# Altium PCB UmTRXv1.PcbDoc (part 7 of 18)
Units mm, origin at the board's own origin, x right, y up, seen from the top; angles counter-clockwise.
Board outline 172 x 113 mm, 6 copper layers (Top Layer, GND, MidLayer1, Mid-Layer 2, InternalPlane2, Bottom Layer); 766 components, 613 nets, 3008 pads, 1360 vias.
Unrouted connection lines stored in the file: 2.
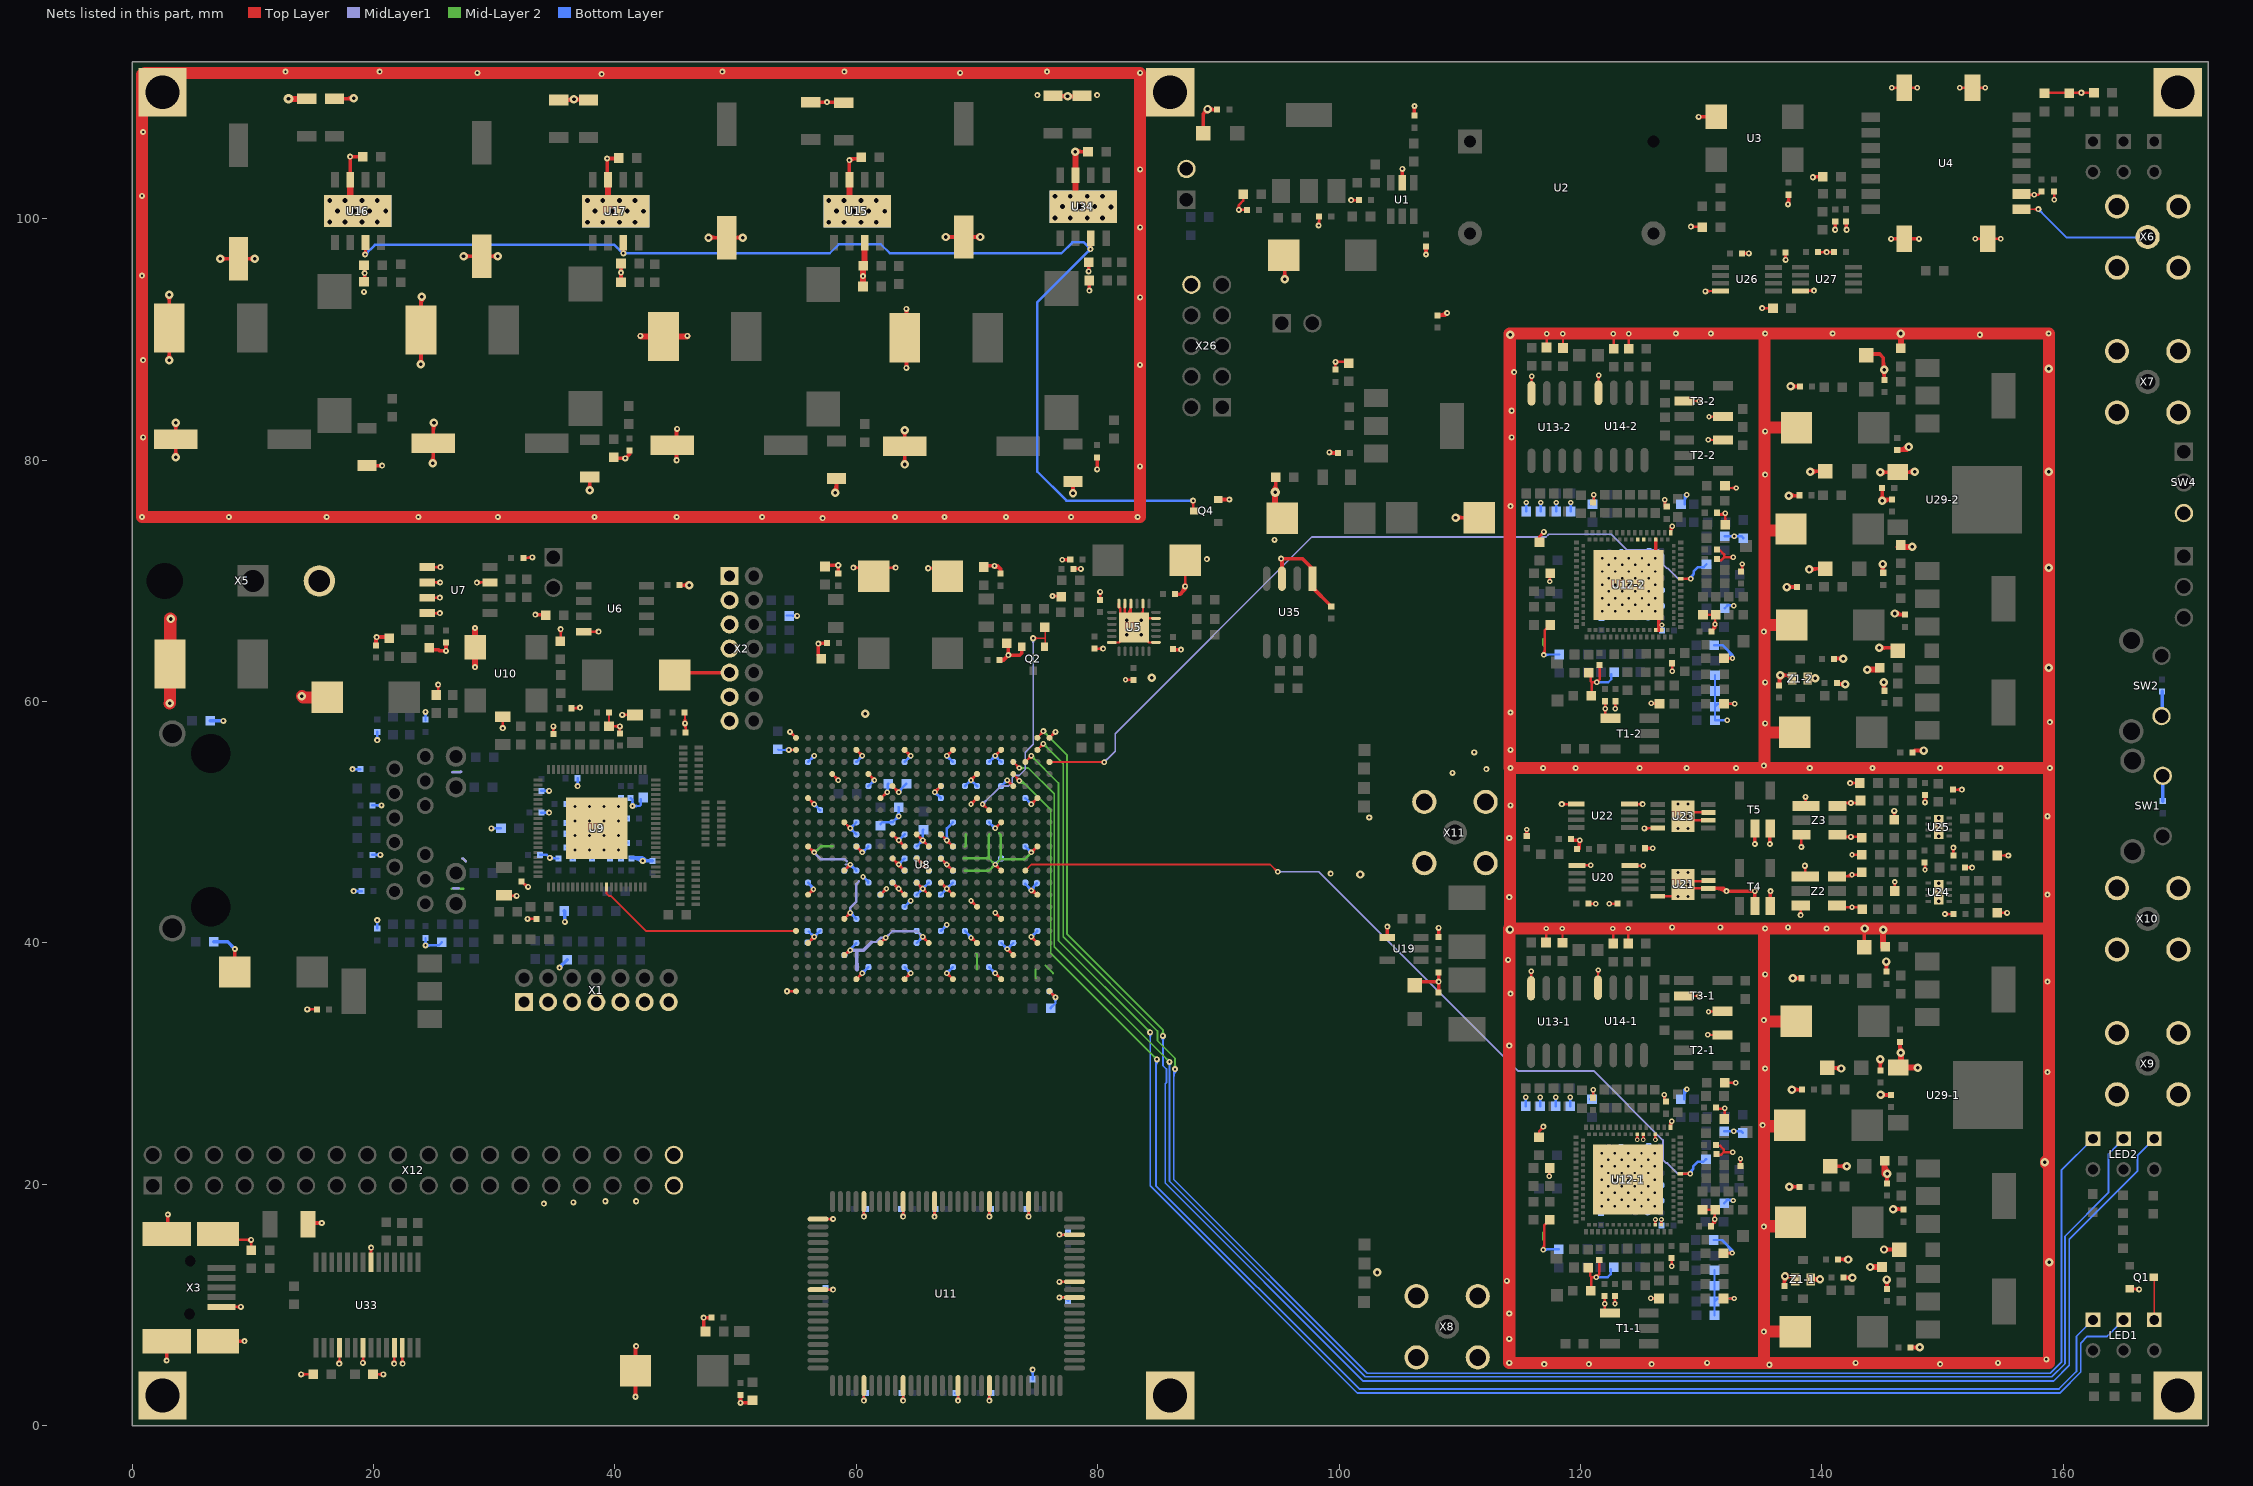
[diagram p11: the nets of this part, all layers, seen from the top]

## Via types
v1: diameter 0.45, hole 0.2, Top Layer to Bottom Layer, tented both sides, 554 vias
v2: diameter 0.5, hole 0.2, Top Layer to Bottom Layer, tented both sides, 468 vias
v3: diameter 0.7, hole 0.3, Top Layer to Bottom Layer, tented both sides, 206 vias
v4: diameter 0.4, hole 0.2, Top Layer to Bottom Layer, tented both sides, 82 vias
v5: diameter 0.8, hole 0.3, Top Layer to Bottom Layer, tented both sides, 16 vias
v6: diameter 0.6, hole 0.25, Top Layer to Bottom Layer, tented both sides, 16 vias
v7: diameter 0.5, hole 0.3, Top Layer to Bottom Layer, tented both sides, 8 vias
v8: diameter 0.7, hole 0.3, Top Layer to Bottom Layer, 4 vias
v9: diameter 0.6, hole 0.3, Top Layer to Bottom Layer, tented both sides, 4 vias
v10: diameter 0.5, hole 0.2, Top Layer to Bottom Layer, 2 vias

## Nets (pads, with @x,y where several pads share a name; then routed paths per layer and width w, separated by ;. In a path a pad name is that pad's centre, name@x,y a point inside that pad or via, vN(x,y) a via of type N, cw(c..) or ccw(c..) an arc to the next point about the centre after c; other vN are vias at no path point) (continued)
GND: (continued)
  Top Layer w0.3: v2(2.85,5.4) X3.0@2.85,7 ; X3.0@2.85,15.9 2.95,16 v2(2.95,17.5) ; v3@2.909,88.441 ccw(c2.516,88.834) 3.071,88.834 ; v3@2.909,93.559 cw(c2.516,93.166) 3.071,93.166 ; v3(3.05,88.3) 3.071,88.321 D2.1@3.071,90.95 3.071,93.679 v3(3.05,93.7) ; 3.071,88.732 ccw(c3.482,88.732) v3@3.191,88.441 ; 3.071,93.268 cw(c3.482,93.268) v3@3.191,93.559 ; v3@3.459,80.391 ccw(c3.117,80.733) 3.6,80.733 ccw(c4.083,80.733) v3@3.741,80.391 ; v3@3.459,82.959 cw(c3.117,82.617) 3.6,82.617 cw(c4.083,82.617) v3@3.741,82.959 ; v3(3.6,80.25) C140.2@3.6,81.75 v3(3.6,83.1) ; X3.0@7.1,7 v2(9.3,7) ; v3(7.3,96.7) C115.2@8.8,96.7 v3(10.15,96.7) ; v3@7.441,96.559 cw(c7.783,96.217) 7.783,96.7 cw(c7.783,97.183) v3@7.441,96.841 ; C171.2@8.5,37.6 v2(8.5,39.5) ; v3@10.009,96.559 ccw(c9.667,96.217) 9.667,96.7 ccw(c9.667,97.183) v3@10.009,96.841 ; C317.2@14.625,16.8 v2(15.7,16.8) ; C119.2@16.75,109.95 18.3,109.95 v3(18.35,110) ; 17.746,109.95 ccw(c17.746,110.604) v3@18.209,110.141 ; 17.988,109.95 cw(c17.988,109.638) v3@18.209,109.859 ; U16.7@18.065,103.305 18.05,103.32 v2(18.05,105.15) R129.1@19.1,105.15 ; R132.2@19.25,94.7 C129.2@19.25,95.75 ; C137.2@19.85,79.55 v2(20.7,79.55) ; C157.2@20.2,64.65 20.2,65.3 v2(20.25,65.35) 21.2,65.35 C163.2@21.3,65.25 ; 20.2,64.988 cw(c20.612,64.988) v2@20.321,65.279 ; v3@23.759,88.091 ccw(c23.366,88.484) 23.921,88.484 ; v3(23.9,87.95) 23.921,87.971 D3.1@23.921,90.8 23.921,93.471 v3(24,93.55) ; 23.921,88.382 ccw(c24.332,88.382) v3@24.041,88.091 ; 23.921,92.876 cw(c24.674,92.876) v3@24.141,93.409 ; C152.2@24.6,64.45 24.75,64.3 25.4,64.3 25.5,64.2 v2(26,64.2) C144.2@26,64.9 ; v3@24.759,79.891 ccw(c24.296,80.354) 24.95,80.354 ; v3@24.859,82.959 cw(c24.638,82.738) 24.95,82.738 ; v3(24.9,79.75) 24.95,79.8 C142.2@24.95,81.4 24.95,83.05 v3(25,83.1) ; 24.95,80.112 ccw(c25.262,80.112) v3@25.041,79.891 ; 24.95,82.496 cw(c25.604,82.496) v3@25.141,82.959 ; v3(27.45,96.9) C116.2@28.95,96.9 v3(30.3,96.9) ; v3@27.591,96.759 cw(c27.933,96.417) 27.933,96.9 cw(c27.933,97.383) v3@27.591,97.041 ; v3@30.159,96.759 ccw(c29.817,96.417) 29.817,96.9 ccw(c29.817,97.383) v3@30.159,97.041 ; v2(33.4,67.2) 34.2,67.2 R25.2@34.25,67.15 ; C124.2@35.35,109.85 36.55,109.85 v3(36.6,109.9) 37.75,109.9 C120.2@37.8,109.85 ; C124.2@35.996,109.85 ccw(c35.996,110.504) v3@36.459,110.041 ; 36.238,109.85 cw(c36.238,109.538) v3@36.459,109.759 ; v3@36.741,109.759 cw(c37.083,109.417) 37.083,109.9 cw(c37.083,110.383) v3@36.741,110.041 ; v3@37.759,77.641 ccw(c37.417,77.983) 37.9,77.983 ccw(c38.383,77.983) v3@38.041,77.641 ; v3(37.9,77.5) C138.2@37.9,78.6 ; v2@39.279,104.929 cw(c39.077,104.727) 39.363,104.727 ; U17.7@39.363,103.452 39.363,104.987 v2(39.35,105) 40.3,105 R130.1@40.35,105.05 ; C154.2@39.9,80.25 40,80.15 v2(40.85,80.15) 41.2,80.5 C148.2@41.2,80.8 ; R133.2@40.5,94.75 v2(40.5,95.55) C130.2@40.5,96.3 ; v2(41.7,2.4) C168.2@41.7,4.55 41.7,6.55 v2(41.75,6.6) ; 41.7,6.238 cw(c42.112,6.238) v2@41.821,6.529 ; C38.2@44.95,62.2 45.15,62.4 X2.9@49.3,62.4 ; v2(45.1,80) 45.1,82.55 v2(45.15,82.6) ; 45.1,82.238 cw(c45.512,82.238) v2@45.221,82.529 ; C25.2@45.354,69.648 46.148,69.648 v3(46.15,69.65) ; 45.662,69.648 ccw(c45.662,70.138) v3@46.009,69.791 ; 45.672,69.648 cw(c45.672,69.172) v3@46.009,69.509 ; C153.2@47.5,7.8 47.35,7.95 v2(47.35,8.95) C145.2@48,8.95 ; v3(47.75,98.45) C114.2@49.25,98.45 v3(50.6,98.45) ; v3@47.891,98.309 cw(c48.233,97.967) 48.233,98.45 cw(c48.233,98.933) v3@47.891,98.591 ; C158.2@50.4,2.55 v2(50.4,1.9) 51.2,1.9 C164.2@51.4,2.1 ; v3@50.459,98.309 ccw(c50.117,97.967) 50.117,98.45 ccw(c50.117,98.933) v3@50.459,98.591 ; C118.2@56.215,109.668 v2(57.565,109.668) 58.915,109.668 C122.2@58.965,109.618 ; v2@56.921,64.729 cw(c57.212,64.438) 57.212,64.85 ; C162.2@57.1,63.55 56.85,63.8 v2(56.85,64.8) 56.8,64.85 C156.2@57.55,64.85 ; C151.2@57.4,71.2 57.5,71.3 v2(58.5,71.3) C143.2@58.5,70.65 ; v3@58.109,77.441 ccw(c57.526,78.024) 58.35,78.024 ; v3(58.25,77.3) 58.35,77.3 58.4,77.35 58.35,77.4 C136.2@58.35,78.5 ; U15.7@59.403,103.289 59.403,104.906 59.415,104.918 v2(59.415,104.868) 59.534,104.987 R128.1@60.39,104.987 ; 59.403,104.598 cw(c59.685,104.598) 59.486,104.797 cw(c59.943,104.34) 59.943,104.987 ; v3@63.859,79.791 ccw(c63.517,80.133) 64,80.133 ccw(c64.483,80.133) v3@64.141,79.791 ; v3@63.859,82.359 cw(c63.517,82.017) 64,82.017 cw(c64.483,82.017) v3@64.141,82.359 ; v3(64,79.65) C131.2@64,81.15 v3(64,82.5) ; v2(64.15,87.65) v2(64.15,92.55) ; v3(67.4,98.5) C117.2@68.9,98.5 v3(70.25,98.5) ; v3@67.541,98.359 cw(c67.883,98.017) 67.883,98.5 cw(c67.883,98.983) v3@67.541,98.641 ; v3@70.109,98.359 ccw(c69.767,98.017) 69.767,98.5 ccw(c69.767,98.983) v3@70.109,98.641 ; C150.2@70.55,71.15 70.65,71.25 v2(71.45,71.25) 71.7,71.25 71.95,71 ; v2@71.468,71.152 cw(c71.564,70.614) 71.95,71 ; C159.2@71.85,63.45 72.2,63.45 v2(72.6,63.85) ; C147.2@71.95,70.6 71.95,71 ; C161.2@72.45,64.85 72.6,64.7 v2(72.6,63.85) ; Q2.2@73.7,64.55 73.7,64 73.55,63.85 v2(72.6,63.85) ; C126.2@76.3,110.2 77.45,110.2 v3(77.5,110.15) 78.65,110.15 C121.2@78.7,110.2 ; C126.2@76.896,110.2 cw(c76.896,109.546) v3@77.359,110.009 ; v1(77.073,71.762) C18.2@77.723,71.762 ; 77.138,110.2 ccw(c77.138,110.512) v3@77.359,110.291 ; v3@77.641,110.009 cw(c77.983,109.667) 77.983,110.15 cw(c77.983,110.633) v3@77.641,110.291 ; v3@77.809,77.391 ccw(c77.467,77.733) 77.95,77.733 ccw(c78.433,77.733) v3@78.091,77.391 ; v3(77.95,77.25) C261.2@77.95,78.25 ; v3(78.15,105.575) R168.1@79.2,105.575 ; U34.7@78.163,103.602 78.163,101.632 U34.0@78.798,100.997 ; v3@78.291,105.434 cw(c78.633,105.092) 78.633,105.575 cw(c78.633,106.058) v3@78.291,105.716 ; v2(79.25,95.65) C266.2@79.25,96.4 ; v2(79.3,94.05) R169.2@79.3,94.9 ; v2@79.946,79.446 C113.2@79.946,80.246 ; C20.2@86.25,64.35 86.3,64.3 v2(86.9,64.3) ; C21.2@86.4,68.9 86.85,68.9 87.25,69.3 v2(87.25,69.55) ; 86.903,68.953 ccw(c86.305,69.55) v2@87.15,69.55 ; C12.2@88.75,107.15 88.75,108.7 ; 88.844,108.794 cw(c89.1,108.538) v3@89.1,108.9 ; v3@88.9,109.09 cw(c88.386,109.064) 88.75,108.7 ; v3@89.241,108.959 cw(c89.462,108.738) 89.462,109.05 ; v3@89.241,109.241 ccw(c89.704,109.704) C13.2@89.704,109.05 ; C13.2@89.9,109.05 89.15,109.05 v3@89.125,109.075 ; Q4.2@90,76.75 v2(90.9,76.75) ; v5@94.523,77.527 ccw(c93.976,78.074) 94.75,78.074 ; v5(94.7,77.35) 94.75,77.4 C269.2@94.75,78.6 ; 94.75,77.833 ccw(c95.183,77.833) v5@94.877,77.527 ; v2@95.129,71.779 cw(c94.802,71.452) 95.265,71.452 ; v2(95.2,71.85) 96.95,71.85 97.8,71 U35.1@97.8,70.197 97.8,69.45 C279.2@99.35,67.9 ; U35.3@95.265,70.191 v2@95.265,71.785 ; v3@95.359,95.141 ccw(c95.017,95.483) 95.5,95.483 ccw(c95.983,95.483) v3@95.641,95.141 ; C6.2@95.4,97 95.5,96.9 v3(95.5,95) ; v2(99.2,80.65) 99.25,80.6 C127.2@99.9,80.6 ; v2@99.271,80.721 ccw(c99.562,81.012) 99.562,80.6 ; U19.4@103.976,40.45 U19.4@103.989,40.463 ; U19.4@104,40.5 v2(104,41.35) ; U1.2@105.239,102.985 v2(105.239,104.15) ; C5.1@106.239,108.55 106.239,109.389 106.25,109.4 v2(106.25,109.35) ; 106.239,109.082 cw(c106.518,109.082) v2@106.321,109.279 ; C169.2@106.25,36.5 106.55,36.8 v2(108.25,36.8) ; v2(107.2,97.05) C8.2@107.2,97.7 ; C139.2@108.15,92 108.75,92 v2(108.95,92.2) ; C139.2@108.226,92 ccw(c108.226,92.924) v2@108.879,92.271 ; C160.2@108.25,35.9 v2(108.25,36.8) ; C155.2@108.25,37.55 v2(108.25,36.8) ; C149.1@108.25,40.5 v2(108.25,41.25) ; v3(109.65,75.25) C146.2@111.6,75.25 ; v3@109.791,75.109 cw(c110.133,74.767) 110.133,75.25 cw(c110.133,75.733) v3@109.791,75.391 ; C289.2@115.55,48.85 v1(115.55,49.4) ; C295.1@119.2,48.5 v1(119.95,48.5) 119.9,48.45 C288.2@119.9,47.8 ; 119.9,48.198 cw(c120.252,48.198) v1@120.003,48.447 ; C293.2@125.35,47.85 v1(126,47.85) ; U12-2.53@126.246,65.93 126.5,65.93 ; U12-2.93@126.246,73.43 126.246,72.3 U12-2.0@123.996,69.68 126.55,66.95 126.5,66.9 126.5,65.93 ; U12-2.55@126.746,65.93 126.5,65.93 ; v2(129.8,108.45) 129.8,108.5 129.844,108.456 U3.2@131.25,108.456 ; v2@129.871,108.379 cw(c130.056,108.194) 130.056,108.456 ; U21.6@130.6,44.525 131.875,44.525 v2(132.1,44.3) v2(134.45,44.3) T4.2@134.45,43.075 ; 131.315,44.525 cw(c131.315,43.515) v2@132.029,44.229 ; v2(134.45,48.2) T5.2@134.45,49.475 ; v2(135.7,48.2) T5.1@135.7,49.475 ; T4.1@135.72,43.075 135.72,44.27 v2(135.75,44.3) ; 135.72,43.986 cw(c136.064,43.986) v2@135.821,44.229 ; v3@136.405,62.04 cw(c136.2,61.835) 136.49,61.835 ; C46-2.2@136.49,61.376 136.49,62.064 136.46,62.094 v3(136.547,62.181) 137.135,62.181 Z1-2.2@137.39,61.926 ; C46-2.2@136.49,61.562 cw(c137.166,61.562) 136.688,62.04 cw(c137.03,61.698) 137.03,62.181 cw(c137.03,62.664) v3@136.688,62.323 ; v3@136.805,12.244 cw(c136.6,12.039) 136.89,12.039 ; C46-1.2@136.89,11.581 136.89,12.269 136.86,12.299 v3(136.947,12.386) 137.535,12.386 Z1-1.2@137.79,12.131 ; C46-1.2@136.89,11.766 cw(c137.566,11.766) 137.088,12.244 cw(c137.43,11.903) 137.43,12.386 cw(c137.43,12.869) v3@137.088,12.527 ; v3(137.101,69.494) C49-2.2@137.944,69.494 ; v2@137.129,101.271 ccw(c136.838,101.562) 137.25,101.562 ; v2(137.2,101.2) 137.25,101.25 C275.1@137.25,102 ; v3@137.243,69.353 cw(c137.584,69.011) 137.584,69.494 cw(c137.584,69.977) v3@137.243,69.635 ; v3(137.275,77.066) C47-2.2@138.096,77.066 ; v3(137.301,19.795) C49-1.2@138.144,19.795 ; v3(137.408,86.12) 137.451,86.12 C50-2.2@138.121,86.12 ; v3@137.416,76.924 cw(c137.758,76.582) 137.758,77.066 ; v3@137.416,77.207 ccw(c137.757,77.548) 137.757,77.066 ; v3@137.443,19.653 cw(c137.784,19.312) 137.784,19.795 cw(c137.784,20.278) v3@137.443,19.936 ; v3(137.525,27.853) C47-1.2@138.346,27.853 ; v3@137.549,85.979 cw(c137.891,85.637) 137.891,86.12 cw(c137.891,86.603) v3@137.549,86.261 ; v3(137.598,37.076) 137.641,37.076 C50-1.2@138.311,37.076 ; v3@137.666,27.711 cw(c138.008,27.369) 138.008,27.853 ; v3@137.666,27.994 ccw(c138.007,28.335) 138.007,27.853 ; v3@137.739,36.934 cw(c138.081,36.593) 138.081,37.076 cw(c138.081,37.559) v3@137.739,37.217 ; Z1-2.2@138.69,61.926 139.443,61.926 v3(139.448,61.921) ; v3(138.95,70.95) 139,71 C66-2.2@140.3,71 ; Z1-2.2@138.953,61.926 cw(c138.953,61.426) v3@139.307,61.78 ; Z1-2.2@138.978,61.926 ccw(c138.978,62.391) v3@139.307,62.062 ; v3(139.05,79.05) 139.2,79.05 139.25,79.1 C64-2.2@140.3,79.1 ; Z1-1.2@139.09,12.131 139.843,12.131 v3(139.848,12.126) ; v3@139.091,70.809 cw(c139.554,70.346) 139.554,71 ; v3@139.091,71.091 ccw(c139.312,71.312) 139.312,71 ; v3@139.191,78.909 cw(c139.654,78.446) 139.654,79.1 ; v3@139.191,79.191 ccw(c139.412,79.412) 139.412,79.1 ; v2(139.25,103.45) 139.25,103.5 139.253,103.503 R9.1@140.086,103.503 ; v2@139.321,103.379 cw(c139.619,103.081) 139.619,103.503 ; Z1-1.2@139.353,12.131 cw(c139.353,11.63) v3@139.707,11.984 ; Z1-1.2@139.378,12.131 ccw(c139.378,12.596) v3@139.707,12.267 ; C64-1.2@140.45,29.65 141.55,29.65 v3(141.6,29.6) ; C66-1.2@140.7,21.5 v3(142.05,21.5) ; C44-2.2@140.94,63.576 141.779,63.576 v3(141.788,63.567) ; C64-1.2@140.996,29.65 cw(c140.996,28.996) v3@141.459,29.459 ; v2@141.029,99.171 ccw(c140.832,99.368) 141.111,99.368 ; v2(141.1,99.1) 141.111,99.111 C11.2@141.111,99.78 ; 141.238,29.65 ccw(c141.238,29.962) v3@141.459,29.741 ; C48-2.2@141.264,61.45 v3(141.95,61.45) ; 141.283,63.576 cw(c141.283,63.062) v3@141.646,63.426 ; 141.327,63.576 ccw(c141.327,64.028) v3@141.646,63.709 ; C44-1.2@141.34,13.781 142.179,13.781 v3(142.188,13.772) ; 141.683,13.781 cw(c141.683,13.267) v3@142.046,13.63 ; v3@141.726,61.376 141.744,61.358 v3@141.787,61.358 ; 141.727,13.781 ccw(c141.727,14.233) v3@142.046,13.913 ; C48-1.2@141.79,12.281 142.476,12.281 142.494,12.263 v3(142.538,12.263) ; v3@141.809,61.309 ccw(c141.467,60.967) 141.467,61.45 ccw(c141.467,61.933) v3@141.809,61.591 ; v3@141.909,21.359 ccw(c141.567,21.017) 141.567,21.5 ccw(c141.567,21.983) v3@141.909,21.641 ; C48-1.2@142.011,12.281 cw(c142.011,11.736) v3@142.396,12.121 ; 142.019,99.416 ccw(c142.366,99.416) v2@142.121,99.171 ; C10.2@142.019,99.799 142.019,99.131 v2(142.05,99.1) ; 142.098,12.281 ccw(c142.098,12.702) v3@142.396,12.404 ; v3@143.409,41.059 cw(c143.188,40.838) 143.5,40.838 ; C67-1.2@143.5,39.65 143.5,41.1 143.4,41.2 v3(143.55,41.2) ; 143.5,40.596 cw(c144.154,40.596) v3@143.691,41.059 ; C67-2.2@143.85,88.8 144.8,88.8 145.1,88.5 145.1,87.567 v3(145.161,87.506) 145.161,87.333 C72-2.2@145.161,86.663 ; v3@144.709,30.209 cw(c144.367,29.867) 144.85,29.867 cw(c145.333,29.867) v3@144.991,30.209 ; v3(144.75,64.45) 146.05,64.45 C65-2.2@146.3,64.2 ; C69-1.2@144.85,29.45 v3(144.85,30.35) ; v3(144.85,79) 147.65,79 v3(147.7,79.05) ; v3@144.859,76.791 ccw(c144.517,77.133) 145,77.133 ccw(c145.483,77.133) v3@145.141,76.791 ; v3(144.866,27.42) 144.888,27.398 C55-1.2@145.644,27.398 ; v3@144.89,71.309 v3@144.908,71.327 ; v3@144.891,64.309 cw(c145.233,63.967) 145.233,64.45 cw(c145.233,64.933) v3@144.891,64.591 ; v3@144.909,71.259 cw(c144.567,70.917) 145.05,70.917 cw(c145.533,70.917) v3@145.191,71.259 ; v3@144.991,78.859 cw(c145.333,78.517) 145.333,79 cw(c145.333,79.483) v3@144.991,79.141 ; v3(145,76.65) C69-2.2@145,77.7 ; v3@145.001,61.466 cw(c144.665,61.131) C70-2.2@145.14,61.131 ; v3@145.008,27.278 cw(c145.297,26.989) 145.297,27.398 ; v3@145.008,27.561 ccw(c145.401,27.955) 145.401,27.398 ; v3@145.019,87.365 cw(c144.678,87.023) 145.161,87.023 cw(c145.643,87.023) v3@145.302,87.365 ; C71-2.2@145.05,70.7 v3(145.05,71.4) v3@145.05,71.483 ; v3@145.094,76.758 C55-2.2@145.85,76.758 ; 145.1,88.135 ccw(c145.79,88.135) v3@145.302,87.648 ; C70-2.2@145.14,60.826 145.14,61.519 145.143,61.521 v3(145.143,61.608) ; C70-2.2@145.14,61.119 cw(c145.631,61.119) v3@145.284,61.466 ; v3@145.141,76.509 cw(c145.744,75.906) C55-2.2@145.744,76.758 ; v3(145.15,14.6) C65-1.2@146.4,14.6 ; v3@145.2,20.877 v3(145.408,20.877) 145.39,20.86 C71-1.2@145.39,20.077 ; v3@145.209,38.321 cw(c144.868,37.979) 145.351,37.979 cw(c145.834,37.979) v3@145.492,38.321 ; v3@145.251,11.971 cw(c144.915,11.635) 145.39,11.635 ; v3@145.266,20.736 cw(c144.967,20.436) 145.39,20.436 ; v3@145.291,14.459 cw(c145.633,14.117) 145.633,14.6 cw(c145.633,15.083) v3@145.291,14.741 ; C72-1.2@145.351,37.619 145.351,38.289 v3(145.351,38.462) ; C70-1.2@145.39,11.331 145.39,12.023 145.393,12.026 v3(145.393,12.112) ; 145.39,11.624 cw(c145.881,11.624) v3@145.534,11.971 ; 145.39,20.353 cw(c145.932,20.353) v3@145.549,20.736 ; v2(145.75,98.35) U4.17@146.84,98.35 v2(148.05,98.35) ; v3(145.9,17.95) 146.7,17.95 C57-1.2@146.75,17.9 ; v3@146.041,17.809 cw(c146.383,17.467) 146.383,17.95 cw(c146.383,18.433) v3@146.041,18.091 ; v3(146.05,67.3) 146.15,67.2 C57-2.2@146.9,67.2 ; v3@146.191,67.441 ccw(c146.774,68.024) C57-2.2@146.774,67.2 ; 146.477,31.559 ccw(c147.209,31.559) v3@146.691,31.041 ; C58-1.2@146.477,31.811 146.477,30.973 v3(146.55,30.9) ; 146.883,80.85 ccw(c146.883,81.359) v3@147.277,81.037 ; v3@147.045,81.227 cw(c146.25,81.878) C58-2.2@146.25,80.85 v3@147.093,80.85 ; U29-2.1@147.096,79 ccw(c147.096,79.654) v3@147.559,79.191 ; 147.338,79 cw(c147.338,78.688) v3@147.559,78.909 ; C56-1.2@147.348,6.489 v3(148.104,6.489) ; 147.531,41.2 147.574,41.157 ; C56-2.2@147.698,55.944 v3(148.454,55.944) ; v3@147.962,6.348 ccw(c147.621,6.007) 147.621,6.489 ccw(c147.621,6.972) v3@147.962,6.631 ; v3@148.312,55.803 ccw(c147.971,55.461) 147.971,55.944 ccw(c147.971,56.427) v3@148.312,56.086 ; 88.75,108.7 v3@89.125,109.075 ; v3@89.125,109.075 89.15,109.1 v3(89.1,109.1) v3@89.125,109.075
  Top Layer w0.5: v5(12.95,109.95) C123.2@14.45,109.95 ; U16.0@18.063,101.282 U16.7@18.063,103.252 ; v2(28.4,62.85) 28.41,62.86 U10.2@28.41,64.5 28.41,66.09 v2(28.4,66.1) ; U17.0@39.423,101.269 U17.7@39.423,103.239 ; v2(42.1,90.3) 42.15,90.25 D1.1@44.021,90.25 45.95,90.25 v2(46,90.3) ; U15.0@59.423,101.269 U15.7@59.423,103.239 ; R131.2@60.55,94.4 60.565,94.415 C128.2@60.565,96.118 60.693,96.246 U15.3@60.693,98.029 ; U34.0@78.15,101.645 v3(78.15,105.575) ; v5(94.7,77.35) 94.7,75.8 C125.2@95.3,75.2 ; v3(143.757,62.647) R96-2.1@144.739,62.647 ; v3(144.007,13.152) R96-1.1@144.989,13.152 ; R98-1.1@145.05,39.65 145.05,40.747 ; 145.05,40.738 cw(c145.462,40.738) v3@145.171,41.029 ; 145.05,40.743 cw(c145.45,40.743) v3@145.17,41.029 ; v3@145.2,20.85 145.2,20.877 R97-1.1@145.2,22.092 ; R97-1.1@145.2,21.62 ccw(c146.15,21.62) v3@145.478,20.948 ; R97-2.1@146.34,72.826 v3@147.583,72.826 ; v3(146.55,30.9) 146.55,29.885 U29-1.1@146.35,29.685 147.915,29.685 v3(147.95,29.65) ; R98-2.1@146.552,89.272 v3@146.552,90.369 ; v3(147.497,72.826) v3@147.583,72.826 ; v3@158.408,21.908 v3(158.471,21.846) ; v3@158.742,87.5 v3(158.81,87.568) ; v3@158.745,62.728 v3(158.81,62.793) ; v3@158.747,71.15 v3(158.81,71.087) ; v3@158.774,79 v3(158.81,79.035)
  Top Layer w1: pad.0@0.808,111.95 v2(0.808,101.9) v2(0.808,95.3) v2(0.808,75.3) v2(8,75.3) v2(16.1,75.3) v2(23.7,75.3) v2(30.3,75.3) v2(38.3,75.3) v2(45.1,75.3) v2(52.2,75.3) v2(63.2,75.3) v2(67.3,75.3) v2(72.4,75.3) v2(77.8,75.3) v2(83.3,75.3) 83.508,75.3 83.508,87.9 v2(83.508,93.5) v2(83.508,99.3) v2(83.508,104.1) v2(83.508,112.1) 12.7,112.1 pad.0@1.064,112.1 ; v3(3.1,59.85) 3.121,59.871 D5.1@3.121,63.1 3.15,63.129 3.15,66.9 v3(3.2,66.85) ; v3(14.05,60.45) 14.15,60.35 C167.2@16.15,60.35 ; v3@114.15,41.323 v2@114.15,54.492 ; v2@114.15,54.6 v2@114.15,54.492 ; C52-2.2@137.75,57.45 135.297,57.45 135.247,57.5 ; C52-1.2@137.8,7.8 135.308,7.8 v2@135.208,7.7 ; C53-1.2@137.89,16.527 135.285,16.527 v2@135.208,16.45 ; C54-1.2@137.89,33.506 135.264,33.506 v2@135.208,33.45 ; C53-2.2@137.9,66.35 135.297,66.35 135.247,66.3 ; C54-2.2@137.9,82.7 135.297,82.7 135.247,82.75 ; C51-2.2@137.99,74.176 135.271,74.176 135.247,74.2 ; C51-1.2@138.04,24.813 135.321,24.813 v2@135.208,24.7 ; v3@143.4,41.2 v2(140.4,41.2) v2(135.3,41.2) v2@135.208,41.2 ; v3(143.55,41.2) 147.531,41.2 158.771,41.2 ; v3@158.577,21.74 ccw(c158.015,22.302) 158.81,22.302 ; v3@158.577,21.952 cw(c158.015,21.389) 158.81,21.389 ; v2@114.15,54.492 119.6,54.492 v2@135.247,54.492 ; v2@114.15,54.492 114.139,54.492 114.139,90.405 114.139,90.492 v1(117.207,90.492) v1(118.528,90.492) v1(122.708,90.492) v1(123.986,90.492) v2@135.247,90.492 ; 135.208,5.2 v2(142.8,5.2) v2(154.6,5.2) 158.81,5.2 158.81,21.846 v2@158.81,54.492 ; 135.208,5.2 v2(130.5,5.2) v2(114.1,5.2) 114.1,41.114 114.1,41.2 v1(117.168,41.2) v1(118.489,41.2) v1(122.669,41.2) v1(123.947,41.2) v2@135.208,41.2 ; 135.208,5.2 v2@135.208,7.7 ; v2@135.208,7.7 v2@135.208,16.45 ; v2@135.208,16.45 v2@135.208,24.7 ; v2@135.208,24.7 v2@135.208,33.45 ; v2@135.208,33.45 v2@135.208,41.2 ; v2@135.247,54.492 135.247,57.5 ; v2@135.247,54.492 v2@158.81,54.492 ; 135.247,57.5 135.247,66.3 ; 135.247,66.3 135.247,74.2 ; 135.247,74.2 135.247,82.75 ; 135.247,82.75 v2@135.247,90.492 ; v2@135.247,90.492 158.8,90.492 158.81,90.492 v3(158.81,87.568) v3(158.81,79.035) v3(158.81,71.087) v3(158.81,62.793) v2@158.81,54.492
  Mid-Layer 2 w0.15: 69.9,39.15 70,39.05 70,37.8 ; 74.85,37.8 74.85,37.1 74.9,37.05 ; 75.65,38.15 76.3,37.5 76.3,37.45 ; 116.9,65.2 116.9,64.7 116.95,64.65
  Mid-Layer 2 w0.2: 26.45,44.5 27.45,44.5 ; 26.6,54.2 27.2,54.2 ; 27.35,47 27.4,47 27.65,46.75 ; 56.725,47.675 57.05,48 58.05,48 ; 68.9,47.025 70.975,47.025 ; 68.975,45.975 70.975,45.975 v1(71.5,46.5) ; 68.975,47.95 69.05,48.025 69.05,49.025 ; 71.025,49 70.975,48.95 70.975,47.025 ; 71.825,49.1 71.975,48.95 71.975,46.975 71.925,46.925 ; v1(74.5,47.5) 73.925,46.925 71.925,46.925 ; 116.9,16 116.9,15.45 116.95,15.4 ; v7(149.7,43.45) v7(149.7,43.95) v7(149.7,44.45) v7(149.7,44.95) ; v7(149.701,48.856) v7(149.701,49.356) v7(149.701,49.856) v7(149.701,50.356) ; 70.975,47.025 v1(71.5,46.5) ; v1(71.5,46.5) 71.925,46.925
  MidLayer1 w0.2: 26.5,54.15 27.2,54.15 27.25,54.2 ; 26.6,44.55 27.05,44.55 ; 27.35,47 27.4,47 27.65,46.75 ; v1(56.5,47.5) 57.075,46.925 59.05,46.925 59.2,46.775 ; 59.101,46.5 v1(59.5,46.5) ; v1(59.5,42.5) 59.5,42.925 60,43.425 60,44.9 60.2,45.1 ; 61.25,40.05 61.281,40.081 61.681,40.081 62.05,40.45 v1(62.45,40.45) 62.975,40.975 65.025,40.975 v1(65.5,40.5) ; v7(149.7,43.45) v7(149.7,43.95) v7(149.7,44.45) v7(149.7,44.95) ; v7(149.701,48.856) v7(149.701,49.356) v7(149.701,49.856) v7(149.701,50.356)
  MidLayer1 w0.3: v1(59.5,39.4) 60.05,39.4 ; 60.05,37.8 60.05,38.278 60.025,38.303 60.025,39.375 60.05,39.4 ; 61.25,40.05 60.6,39.4 60.05,39.4
  Bottom Layer w0.2: v2(18.25,54.4) C29.2@18.9,54.4 ; v2(18.35,44.3) C30.2@19,44.3 ; v2@18.356,54.294 cw(c18.612,54.038) 18.612,54.4 cw(c18.612,54.762) v2@18.356,54.506 ; v2@18.456,44.194 cw(c18.712,43.938) 18.712,44.3 cw(c18.712,44.662) v2@18.456,44.406 ; C35.2@19.9,47.3 v2(20.55,47.3) ; C34.2@19.9,51.4 v2(20.65,51.4) ; v2@20.194,41.794 cw(c19.938,41.538) 20.3,41.538 cw(c20.662,41.538) v2@20.406,41.794 ; v2@20.194,56.906 ccw(c19.938,57.162) 20.3,57.162 ccw(c20.662,57.162) v2@20.406,56.906 ; C36.2@20.3,41.2 v2(20.3,41.9) ; v2(20.3,56.8) C33.2@20.3,57.5 ; v2@20.444,47.194 ccw(c20.188,46.938) 20.188,47.3 ccw(c20.188,47.662) v2@20.444,47.406 ; v2@20.544,51.294 ccw(c20.288,51.038) 20.288,51.4 ccw(c20.288,51.762) v2@20.544,51.506 ; v2@24.194,39.906 ccw(c23.938,40.162) 24.3,40.162 ccw(c24.662,40.162) 24.406,39.906 ccw(c24.662,40.162) 24.662,39.8 ccw(c24.662,39.438) v2@24.406,39.694 ; v2@24.194,59.044 cw(c23.938,58.788) 24.3,58.788 cw(c24.662,58.788) v2@24.406,59.044 ; C31.2@24.3,40.4 v2(24.3,39.8) 25.4,39.8 C32.1@25.65,40.05 ; C28.2@24.3,58.45 C28.2@24.3,58.5 v2(24.3,59.15) ; v2(29.75,49.5) R60.2@30.55,49.5 ; v2@29.856,49.394 cw(c30.112,49.138) 30.112,49.5 cw(c30.112,49.862) v2@29.856,49.606 ; C245.2@33.8,47.3 34.35,47.3 v2(34.6,47.05) 34.65,47 C229.2@35.3,47 ; C242.2@33.9,50.8 v2(34.55,50.8) ; C281.2@33.9,52.6 v2(34.55,52.6) ; v2@34.444,50.694 ccw(c34.188,50.438) 34.188,50.8 ccw(c34.188,51.162) v2@34.444,50.906 ; v2@34.444,52.494 ccw(c34.188,52.238) 34.188,52.6 ccw(c34.188,52.962) v2@34.444,52.706 ; v2@34.706,47.156 ccw(c35.083,47.533) C229.2@35.083,47 ; 36.35,47.9 cw(c36.35,47.494) v6(36.7,47.7) ; 36.35,49.1 cw(c36.35,48.694) v6(36.7,48.9) 36.5,49.1 36,49.1 cw(c36,48.488) v6@36.528,48.798 ; 36.35,49.9 ccw(c36.35,50.306) v6(36.7,50.1) 36.5,49.9 36,49.9 ccw(c36,50.512) v6@36.528,50.202 ; 36.35,51.5 cw(c36.35,51.094) v6(36.7,51.3) 36.5,51.5 C241.2@36,51.5 cw(c36,50.888) v6@36.528,51.198 ; C238.2@36.5,46.972 cw(c37.162,46.972) v6@36.807,47.531 ; C238.2@36.5,47 36.5,47.5 v6(36.7,47.7) ; 36.5,47.336 cw(c36.931,47.336) v6(36.7,47.7) ; v6@36.528,47.598 ccw(c36,47.288) C244.2@36,47.9 36.5,47.9 v6(36.7,47.7) ; v2@36.794,53.106 ccw(c36.538,53.362) 36.9,53.362 ccw(c37.262,53.362) v2@37.006,53.106 ; v2(36.9,53) C237.2@36.9,53.65 ; v6@37.793,47.531 cw(c37.438,46.972) C232.2@38.1,46.972 ; C232.2@38.1,47 38.1,47.5 v6(37.9,47.7) cw(c37.669,47.336) 38.1,47.336 ; v6@39.213,47.535 cw(c39.386,47.286) 39.6,47.5 ; 39.43,47.67 ccw(c39.247,47.487) v6(39.1,47.7) 39.4,47.7 39.6,47.5 ; C239.2@39.6,47 39.6,47.5 ; v6@40.193,47.531 cw(c39.838,46.972) C233.2@40.5,46.972 ; v6@40.198,51.472 ccw(c39.888,52) C236.2@40.5,52 40.5,51.5 v6(40.3,51.3) ccw(c40.094,51.65) 40.5,51.65 ; v6@40.3,47.9 ccw(c40.3,48.624) C231.2@40.812,48.112 ; v6@40.472,49.998 cw(c41,49.688) C234.2@41,50.3 40.5,50.3 v6(40.3,50.1) cw(c40.65,49.894) 40.65,50.3 ; C233.2@40.5,47 40.5,47.5 v6(40.3,47.7) ; 40.5,47.336 ccw(c40.069,47.336) v6(40.3,47.7) ; v6@40.5,47.7 cw(c40.741,47.7) 40.571,47.871 ; C231.2@41,48.3 40.4,47.7 v6(40.3,47.7) ; C230.2@41.3,52 41.45,51.85 v2(41.45,51.35) 42.05,51.35 42.15,51.45 C41.1@42.15,51.9 ; v2@41.344,51.456 ccw(c41.088,51.712) 41.45,51.712 ccw(c41.812,51.712) 41.556,51.456 ccw(c41.812,51.712) 41.812,51.35 ccw(c41.812,50.988) v2@41.556,51.244 ; R150.1@54.234,67.133 55.067,67.133 v2(55.1,67.1) ; R150.1@54.658,67.133 cw(c54.658,66.658) v2@54.994,66.994 ; R150.1@54.818,67.133 ccw(c54.818,67.382) v2@54.994,67.206 ; C212.1@56,45 56.5,44.5 v1(56.45,44.45) ; C186.1@56,55 v1(56.5,55.5) ; C185.1@56.05,40.05 v1(56.5,40.5) ; C209.1@56.05,40.95 v1(56.5,40.5) ; C212.1@56.123,44.877 cw(c55.696,44.45) v1@56.3,44.45 ; v1@56.35,55.5 cw(c55.988,55.5) 56.244,55.244 cw(c56.5,54.988) v1@56.5,55.35 ; v1@56.5,40.35 ccw(c56.5,39.988) 56.244,40.244 ccw(c55.988,40.5) 56.35,40.5 ccw(c55.988,40.5) 56.244,40.756 ccw(c56.5,41.012) 56.5,40.65 ccw(c56.5,41.012) 56.756,40.756 ccw(c57.012,40.5) v1@56.65,40.5 ; v1@56.5,51.35 cw(c56.5,50.988) 56.756,51.244 cw(c57.012,51.5) v1@56.65,51.5 ; v1(56.5,51.5) C211.1@57,51 ; v1@56.55,40.45 v1(56.5,40.5) ; v1@56.55,40.5 v1(56.5,40.5) ; C208.1@57,41 v1(56.5,40.5) ; C219.1@57.45,11.4 57.575,11.275 v2(58.075,11.275) ; v2@57.969,11.169 ccw(c57.713,10.913) 57.713,11.275 ccw(c57.713,11.637) v2@57.969,11.381 ; C176.1@59,39 59.5,39.5 C194.1@60,40 ; C210.1@59,46 v1(59.5,46.5) C172.1@60,46 ; C176.1@59.073,39.073 cw(c59.5,38.646) v1@59.5,39.25 ; v1@59.35,46.5 cw(c58.988,46.5) 59.244,46.244 cw(c59.5,45.988) 59.5,46.35 cw(c59.5,45.988) 59.756,46.244 cw(c60.012,46.5) v1@59.65,46.5 ; v1@59.5,42.35 cw(c59.5,41.988) 59.756,42.244 cw(c60.012,42.5) v1@59.65,42.5 ; v1(59.5,42.5) C184.1@60,42 ; v1@59.5,49.35 cw(c59.5,48.988) 59.756,49.244 cw(c60.012,49.5) 59.65,49.5 cw(c60.012,49.5) 59.756,49.756 cw(c59.5,50.012) v1@59.5,49.65 ; v1(59.5,39.4) v1@59.5,39.5 ; v1@59.65,39.4 cw(c60.254,39.4) C194.1@59.827,39.827 ; C213.1@60,48 v1(60.5,47.5) C249.2@61,48 ; C174.1@60,49 v1(59.5,49.5) C177.1@60,50 ; C251.2@60,55 v1(60.5,55.5) ; v1@60.35,47.5 ccw(c59.988,47.5) 60.244,47.756 ccw(c60.5,48.012) 60.5,47.65 ccw(c60.5,48.012) 60.756,47.756 ccw(c61.012,47.5) v1@60.65,47.5 ; v1@60.35,55.5 cw(c59.988,55.5) 60.244,55.244 cw(c60.5,54.988) v1@60.5,55.35 ; v1(60.5,37.5) C187.1@61,38 ; v1@60.5,37.65 ccw(c60.5,38.012) 60.756,37.756 ccw(c61.012,37.5) v1@60.65,37.5 ; v2@60.519,2.181 ccw(c60.263,2.437) 60.625,2.437 ccw(c60.987,2.437) v2@60.731,2.181 ; v2@60.519,17.431 ccw(c60.263,17.687) 60.625,17.687 ccw(c60.987,17.687) v2@60.731,17.431 ; v1@60.55,45.375 cw(c60.55,45.073) 60.763,45.287 cw(c60.977,45.5) v1@60.675,45.5 ; v1(60.55,45.5) 61,45.05 C250.2@61,45 ; v2(60.625,2.075) 60.625,2.525 C218.1@60.8,2.7 ; v2(60.625,17.325) 60.625,17.775 C220.1@60.8,17.95 ; C199.1@61,53 v1(61.5,53.5) ; v1@61.35,53.5 cw(c60.988,53.5) 61.244,53.244 cw(c61.5,52.988) v1@61.5,53.35 ; C248.2@62,44 v1(62.5,44.5) ; R23.1@62,49.85 62.15,50 C257.2@63,50 v1(63.5,50.5) R67.1@63.5,51.25 63.5,51.263 R67.1@63.504,51.266 ; v1@62.35,44.5 cw(c61.988,44.5) 62.244,44.244 cw(c62.5,43.988) v1@62.5,44.35 ; C197.1@63,45 v1(63.5,44.5) ; v1@63.35,44.5 ccw(c62.988,44.5) 63.244,44.756 ccw(c63.5,45.012) v1@63.5,44.65 ; v1@63.35,50.5 cw(c62.988,50.5) 63.244,50.244 cw(c63.5,49.988) v1@63.5,50.35 ; v1@63.394,50.606 ccw(c63.138,50.862) 63.5,50.862 ccw(c63.862,50.862) v1@63.606,50.606 ; v1@63.5,46.35 cw(c63.5,45.988) 63.756,46.244 cw(c64.012,46.5) 63.65,46.5 cw(c64.012,46.5) 63.756,46.756 cw(c63.5,47.012) v1@63.5,46.65 ; v1(63.5,48.5) C265.2@64,49 ; v1@63.5,48.65 ccw(c63.5,49.012) 63.756,48.756 ccw(c64.012,48.5) v1@63.65,48.5 ; v1(63.5,52.5) 63.5,52.55 R32.2@64.15,53.2 ; v1@63.5,52.65 ccw(c63.5,52.891) 63.671,52.721 ; v1@63.65,52.5 cw(c64.133,52.5) R32.2@63.791,52.841 ; C221.1@63.7,17.95 63.875,17.775 v2(63.875,17.325) ; C216.1@63.75,2.7 63.875,2.575 v2(63.875,2.075) ; v2@63.769,2.181 ccw(c63.513,2.437) 63.875,2.437 ccw(c64.237,2.437) v2@63.981,2.181 ; v2@63.769,17.431 ccw(c63.513,17.687) 63.875,17.687 ccw(c64.237,17.687) v2@63.981,17.431 ; C188.1@64,38 v1(64.5,37.5) ; C206.1@64,43 v1(64.5,43.5) ; C273.2@64,46 v1(63.5,46.5) C263.2@64,47 ; C201.1@64,55 v1(64.5,55.5) ; v1@64.35,37.5 ccw(c63.988,37.5) 64.244,37.756 ccw(c64.5,38.012) v1@64.5,37.65 ; v1@64.35,43.5 cw(c63.988,43.5) 64.244,43.244 cw(c64.5,42.988) v1@64.5,43.35 ; v1@64.35,55.5 cw(c63.988,55.5) 64.244,55.244 cw(c64.5,54.988) v1@64.5,55.35 ; C183.1@65,40 v1(65.5,40.5) C246.2@65,41 ; C262.2@65,44 v1(65.5,44.5) ; C274.2@65,45 v1(65.5,44.5) ; C270.2@65,47 v1(65.5,46.5) C264.2@66,46 ; C277.2@65,48 v1(65.5,48.5) ; v1@65.35,46.5 ccw(c64.988,46.5) 65.244,46.756 ccw(c65.5,47.012) v1@65.5,46.65 ; v1@65.35,48.5 cw(c64.988,48.5) 65.244,48.244 cw(c65.5,47.988) 65.5,48.35 cw(c65.5,47.988) 65.756,48.244 cw(c66.012,48.5) v1@65.65,48.5 ; v1@65.5,40.35 ccw(c65.5,39.988) 65.244,40.244 ccw(c64.988,40.5) 65.35,40.5 ccw(c64.988,40.5) 65.244,40.756 ccw(c65.5,41.012) v1@65.5,40.65 ; v1@65.5,44.35 ccw(c65.5,43.988) 65.244,44.244 ccw(c64.988,44.5) 65.35,44.5 ccw(c64.988,44.5) 65.244,44.756 ccw(c65.5,45.012) 65.5,44.65 ccw(c65.5,45.012) 65.756,44.756 ccw(c66.012,44.5) v1@65.65,44.5 ; v1@65.5,46.35 cw(c65.5,45.988) 65.756,46.244 cw(c66.012,46.5) v1@65.65,46.5 ; R24.1@65.566,49.396 65.5,49.33 v1(65.5,48.5) ; C272.2@66,45 v1(65.5,44.5) ; C268.2@66,48 v1(65.5,48.5) ; v2@66.369,17.431 ccw(c66.113,17.687) 66.475,17.687 ccw(c66.837,17.687) v2@66.581,17.431 ; v2(66.475,17.325) 66.475,17.875 C222.1@66.55,17.95 ; v1@66.5,52.35 cw(c66.5,51.988) 66.756,52.244 cw(c67.012,52.5) 66.65,52.5 cw(c67.012,52.5) 66.756,52.756 cw(c66.5,53.012) v1@66.5,52.65 ; C182.1@67,41 v1(67.5,41.5) ; C196.1@67,44 v1(67.5,44.5) C260.2@68,45 ; C276.2@67,47 v1(67.5,46.5) C200.1@68,46 ; C271.2@67,49 v1(67.5,48.5) ; C203.1@67,52 v1(66.5,52.5) C247.2@67,53 ; v1@67.35,41.5 cw(c66.988,41.5) 67.244,41.244 cw(c67.5,40.988) v1@67.5,41.35 ; v1@67.35,44.5 cw(c66.988,44.5) 67.244,44.244 cw(c67.5,43.988) v1@67.5,44.35 ; v1@67.35,46.5 ccw(c66.988,46.5) 67.244,46.756 ccw(c67.5,47.012) v1@67.5,46.65 ; v1@67.35,48.5 ccw(c66.988,48.5) 67.244,48.756 ccw(c67.5,49.012) v1@67.5,48.65 ; v1@67.394,48.606 ccw(c67.138,48.862) 67.5,48.862 ccw(c67.862,48.862) v1@67.606,48.606 ; v1(67.5,37.5) C189.1@68,38 ; v1@67.5,37.65 ccw(c67.5,38.012) 67.756,37.756 ccw(c68.012,37.5) v1@67.65,37.5 ; v1@67.5,44.65 ccw(c67.5,45.012) 67.756,44.756 ccw(c68.012,44.5) v1@67.65,44.5 ; v1@67.5,46.35 cw(c67.5,45.988) 67.756,46.244 cw(c68.012,46.5) v1@67.65,46.5 ; v1@67.5,48.35 cw(c67.5,47.988) 67.756,48.244 cw(c68.012,48.5) v1@67.65,48.5 ; v1@67.5,55.35 cw(c67.5,54.988) 67.756,55.244 cw(c68.012,55.5) v1@67.65,55.5 ; v1(67.5,55.5) C252.2@68,55 ; C255.2@68,48 v1(67.5,48.5) ; C258.2@68,50 67.5,49.5 v1(67.5,48.5) ; C215.1@68.2,2.7 68.425,2.475 v2(68.425,2.075) ; v2@68.319,2.181 ccw(c68.063,2.437) 68.425,2.437 ccw(c68.787,2.437) v2@68.531,2.181 ; C204.1@69,41 v1@69.5,40.5 ; C256.2@69,53 v1(69.5,53.5) C198.1@70,53 ; 69.208,40.792 cw(c68.866,40.45) v1@69.35,40.45 ; 69.33,40.67 ccw(c69.5,40.841) v1@69.5,40.6 ; v1@69.35,53.5 cw(c68.988,53.5) 69.244,53.244 cw(c69.5,52.988) 69.5,53.35 cw(c69.5,52.988) 69.756,53.244 cw(c70.012,53.5) v1@69.65,53.5 ; v1(69.5,40.45) v1@69.5,40.5 ; v2@70.919,2.181 ccw(c70.663,2.437) 71.025,2.437 ccw(c71.387,2.437) v2@71.131,2.181 ; v2@70.919,17.431 ccw(c70.663,17.687) 71.025,17.687 ccw(c71.387,17.687) v2@71.131,17.431 ; C190.1@71,38 v1(71.5,37.5) ; C259.2@71,50 v1(71.5,49.5) ; C202.1@71,55 v1(71.5,55.5) C254.2@72,55 ; v2(71.025,2.075) 71.025,2.525 C217.1@71.2,2.7 ; v2(71.025,17.325) 71.025,17.825 C224.1@71.15,17.95 ; v1@71.35,37.5 ccw(c70.988,37.5) 71.244,37.756 ccw(c71.5,38.012) v1@71.5,37.65 ; v1@71.35,49.5 ccw(c70.988,49.5) 71.244,49.756 ccw(c71.5,50.012) v1@71.5,49.65 ; v1@71.35,55.5 cw(c70.988,55.5) 71.244,55.244 cw(c71.5,54.988) 71.5,55.35 cw(c71.5,54.988) 71.756,55.244 cw(c72.012,55.5) v1@71.65,55.5 ; v1(71.5,46.5) C175.1@72,47 ; v1@71.5,46.65 ccw(c71.5,47.012) 71.756,46.756 ccw(c72.012,46.5) v1@71.65,46.5 ; C193.1@72,40 v1(72.5,39.5) C181.1@73,40 ; C178.1@72,53 v1(72.5,53.5) ; v1@72.35,39.5 ccw(c71.988,39.5) 72.244,39.756 ccw(c72.5,40.012) 72.5,39.65 ccw(c72.5,40.012) 72.756,39.756 ccw(c73.012,39.5) v1@72.65,39.5 ; v1@72.35,53.5 cw(c71.988,53.5) 72.244,53.244 cw(c72.5,52.988) v1@72.5,53.35 ; C205.1@74,44.9 v1@74.45,44.45 ; C192.1@74,48 v1(74.5,47.5) ; C207.1@74,52 v1(74.5,51.5) ; C225.1@74.1,17.95 74.275,17.775 v2(74.275,17.325) ; v2@74.169,17.431 ccw(c73.913,17.687) 74.275,17.687 ccw(c74.637,17.687) v2@74.381,17.431 ; 74.209,44.691 cw(c73.867,44.35) v1@74.35,44.35 ; 74.329,44.571 ccw(c74.5,44.741) v1@74.5,44.5 ; v1@74.35,47.5 ccw(c73.988,47.5) 74.244,47.756 ccw(c74.5,48.012) v1@74.5,47.65 ; v1@74.35,51.5 ccw(c73.988,51.5) 74.244,51.756 ccw(c74.5,52.012) v1@74.5,51.65 ; v2@74.494,4.544 cw(c74.238,4.288) 74.6,4.288 cw(c74.962,4.288) v2@74.706,4.544 ; v1(74.5,40.5) C180.1@75,41 ; v1@74.5,40.65 ccw(c74.5,41.012) 74.756,40.756 ccw(c75.012,40.5) v1@74.65,40.5 ; v1(74.5,44.35) 74.5,44.4 v1@74.45,44.45 ; C223.1@74.6,3.85 v2(74.6,4.65) ; v1@74.65,44.35 cw(c75.374,44.35) C179.1@74.862,44.862 ; C179.1@74.95,44.95 v1@74.45,44.45 ; C191.1@76,36 v2(76.5,35.5) 76.5,35 R93.2@76.1,34.6 ; v2@76.35,35.5 ccw(c75.988,35.5) 76.244,35.756 ccw(c76.5,36.012) v2@76.5,35.65 ; v2@76.394,35.394 cw(c76.138,35.138) 76.5,35.138 cw(c76.862,35.138) v2@76.606,35.394 ; v2(76.825,10.625) 77.275,10.625 C227.1@77.55,10.35 ; v2(76.825,15.825) 77.375,15.825 C226.1@77.55,16 ; v2@76.931,10.519 cw(c77.187,10.263) 77.187,10.625 cw(c77.187,10.987) v2@76.931,10.731 ; v2@76.931,15.719 cw(c77.187,15.463) 77.187,15.825 cw(c77.187,16.187) v2@76.931,15.931 ; v1@115.373,27.12 cw(c115.159,26.906) 115.461,26.906 cw(c115.763,26.906) v1@115.549,27.12 ; v1@115.412,76.412 cw(c115.198,76.198) 115.5,76.198 cw(c115.802,76.198) v1@115.588,76.412 ; R122-1.2@115.461,26.458 v1(115.461,27.208) ; R122-2.2@115.5,75.75 v1(115.5,76.5) ; v1@116.573,27.12 cw(c116.359,26.906) 116.661,26.906 cw(c116.963,26.906) v1@116.749,27.12 ; v1@116.612,76.412 cw(c116.398,76.198) 116.7,76.198 cw(c117.002,76.198) v1@116.788,76.412 ; R120-1.1@116.661,26.458 v1(116.661,27.208) ; R120-2.1@116.7,75.75 v1(116.7,76.5) ; v1@116.956,14.608 R107-1.1@118.211,14.608 ; v1@116.995,63.9 R107-2.1@118.25,63.9 ; v1@117.01,14.485 cw(c117.307,14.188) 117.307,14.608 ; v1@117.049,63.777 cw(c117.346,63.48) 117.346,63.9 ; v1@117.873,27.12 cw(c117.659,26.906) 117.961,26.906 cw(c118.263,26.906) v1@118.049,27.12 ; v1@117.912,76.412 cw(c117.698,76.198) 118,76.198 cw(c118.302,76.198) v1@118.088,76.412 ; R124-1.2@117.961,26.458 v1(117.961,27.208) ; R124-2.2@118,75.75 v1(118,76.5) ; v1@119.073,27.12 cw(c118.859,26.906) 119.161,26.906 cw(c119.463,26.906) v1@119.249,27.12 ; v1@119.112,76.412 cw(c118.898,76.198) 119.2,76.198 cw(c119.502,76.198) v1@119.288,76.412 ; R123-1.1@119.161,26.458 v1(119.161,27.208) ; R123-2.1@119.2,75.75 v1(119.2,76.5) ; C81-1.2@120.811,27.058 121.057,27.304 v1(121.057,27.838) ; C81-2.2@120.85,76.35 121.096,76.596 v1(121.096,77.13) ; v1@120.969,27.75 cw(c120.755,27.536) 121.057,27.536 cw(c121.359,27.536) v1@121.145,27.75 ; v1@121.008,77.041 cw(c120.794,76.828) 121.096,76.828 cw(c121.398,76.828) v1@121.184,77.041 ; v1(121.311,12.308) 122.261,12.308 122.511,12.558 C74-1.2@122.511,12.958 ; v1(121.35,61.6) 122.3,61.6 122.55,61.85 C74-2.2@122.55,62.25 ; v1@121.399,12.22 cw(c121.613,12.006) 121.613,12.308 cw(c121.613,12.61) v1@121.399,12.397 ; v1@121.438,61.512 cw(c121.652,61.298) 121.652,61.6 cw(c121.652,61.902) v1@121.438,61.688 ; C62-1.1@121.707,17.638 121.707,18.138 U12-1.0@121.757,18.188 ; C62-2.1@121.746,66.93 121.746,67.43 U12-2.0@121.796,67.48 ; U12-1.0@122.857,22.588 C88-1.2@123.357,23.088 ; U12-2.0@122.896,71.88 C88-2.2@123.396,72.38 ; U12-1.0@125.057,18.188 C92-1.2@125.557,17.688 ; U12-2.0@125.096,67.48 C92-2.2@125.596,66.98 ; C79-1.2@125.657,23.188 125.657,23.088 U12-1.0@126.157,22.588 ; C79-2.2@125.696,72.48 125.696,72.38 U12-2.0@126.196,71.88 ; U12-1.0@126.157,18.188 126.257,18.188 C89-1.2@126.707,18.638 ; U12-1.0@126.157,20.388 126.607,19.938 C80-1.2@126.707,19.938 ; U12-2.0@126.196,67.48 126.296,67.48 C89-2.2@126.746,67.93 ; U12-2.0@126.196,69.68 126.646,69.23 C80-2.2@126.746,69.23 ; v4@126.636,17.017 cw(c126.466,16.847) 126.707,16.847 cw(c126.948,16.847) v4@126.778,17.017 ; C78-1.2@126.707,16.588 v4(126.707,17.088) ; C78-2.2@126.746,65.88 v4@126.746,66.4 ; C75-1.2@128.611,27.042 v1@128.611,27.858 ; C75-1.2@128.611,27.315 cw(c129.254,27.315) v1@128.799,27.77 ; C75-2.2@128.65,76.334 v1@128.65,77.15 ; C75-2.2@128.65,76.607 cw(c129.293,76.607) v1@128.838,77.062 ; C73-1.2@131.057,15.388 131.731,15.388 132.561,14.558 ; C73-2.2@131.096,64.68 131.77,64.68 132.6,63.85 ; R110-1.1@131.107,9.162 R111-1.1@131.107,10.288 ; R113-1.1@131.107,12.888 R112-1.1@131.107,11.588 R111-1.1@131.107,10.288 ; R113-2.1@131.146,62.18 R112-2.1@131.146,60.88 R111-2.1@131.146,59.58 ; 131.842,58.45 ccw(c131.842,58.791) v1@132.084,58.55 ; 131.898,58.45 cw(c131.898,58.188) v1@132.084,58.373 ; C82-1.2@131.907,18.438 C82-1.2@132.077,18.608 ; C98-1.2@131.911,24.408 v1(132.711,24.408) 133.311,24.408 R121-1.2@133.461,24.258 ; C82-2.2@131.946,67.73 C82-2.2@132.116,67.9 ; C98-2.2@131.95,73.7 v1(132.75,73.7) 133.35,73.7 R121-2.2@133.5,73.55 ; C82-1.2@132.127,18.708 v1@132.711,18.708 ; C82-2.2@132.166,68 v1@132.75,68 ; 132.171,14.948 cw(c131.531,14.308) v1@132.436,14.308 ; v1(132.172,58.462) 132.16,58.45 R110-2.1@131.15,58.45 131.146,58.454 R111-2.1@131.146,59.58 ; 132.21,64.24 cw(c131.57,63.6) v1@132.475,63.6 ; C82-1.2@132.239,18.708 cw(c132.239,18.236) v1@132.573,18.57 ; C82-2.2@132.278,68 cw(c132.278,67.528) v1@132.612,67.862 ; v1@132.486,14.408 ccw(c132.374,14.558) 132.561,14.558 ; 132.512,14.607 cw(c132.214,14.308) v1@132.636,14.308 ; v1@132.525,63.7 ccw(c132.413,63.85) 132.6,63.85 ; 132.551,63.899 cw(c132.253,63.6) v1@132.675,63.6 ; v1(132.561,14.308) 132.561,14.558 ; v1(132.6,63.6) 132.6,63.85 ; v1@132.623,24.32 ccw(c132.409,24.106) 132.409,24.408 ccw(c132.409,24.71) v1@132.623,24.497 ; v1@132.636,14.408 cw(c132.749,14.558) 132.561,14.558 ; v1@132.662,73.612 ccw(c132.448,73.398) 132.448,73.7 ccw(c132.448,74.002) v1@132.662,73.788 ; v1@132.669,10.45 ccw(c132.455,10.236) 132.455,10.538 ccw(c132.455,10.84) v1@132.669,10.626 ; v1@132.675,63.7 cw(c132.787,63.85) 132.6,63.85 ; v1@132.708,59.741 ccw(c132.494,59.528) 132.494,59.83 ccw(c132.494,60.132) v1@132.708,59.918 ; v1(132.757,10.538) 131.357,10.538 R111-1.1@131.107,10.288 ; v1(132.796,59.83) 131.396,59.83 R111-2.1@131.146,59.58 ; v1@132.799,24.32 cw(c133.013,24.106) 133.013,24.408 cw(c133.013,24.71) v1@132.799,24.497 ; v1@132.838,73.612 cw(c133.052,73.398) 133.052,73.7 cw(c133.052,74.002) v1@132.838,73.788 ; v7(149.7,43.45) v7(149.7,43.95) v7(149.7,44.45) v7(149.7,44.95) ; v7(149.701,48.856) v7(149.701,49.356) v7(149.701,49.856) v7(149.701,50.356)
  Bottom Layer w0.3: R40.1@6.45,58.4 v2(7.55,58.4) ; R39.1@6.75,40.1 7.9,40.1 v2(8.5,39.5) ; v2(35.4,37.95) 35.4,37.984 R20.2@36.036,38.62 ; v2@35.5,37.95 cw(c35.823,37.95) 35.595,38.178 ; R61.2@35.8,42.65 35.85,42.6 v2(35.85,41.75) ; C280.2@41.3,47.05 42.05,47.05 v2(42.3,46.8) C235.2@43.1,46.8 ; C280.2@41.455,47.05 cw(c41.455,45.955) v2@42.229,46.729 ; 42.179,47.05 cw(c42.179,46.679) v2@42.441,46.941 ; SW2.1@168.15,58.8 168.2,58.85 C43.1@168.2,60.85 ; C26.2@168.25,51.75 SW1.2@168.25,53.85
  other v1: 116.921,14.574 132.661,18.658 128.825,27.875 116.96,63.865 132.7,67.95 128.8,77.15
  other v2: 135.65,5.05 117,5.1 120.7,5.1 125.9,5.1 149.8,5.1 158.6,5.5 114.1,7.2 135.2,7.8 114.1,9.3 113.9,12 135.2,16.5 34.1,18.4 36.55,18.5 39.2,18.6 41.75,18.6 135.1,24.9 158.7,29.3 135.3,29.6 114.1,31.5 135.2,33.6 114.2,35.8 158.7,36.8 135.3,37.4 114,38.6 127.6,41.3 131.6,41.3 137.2,41.3 114.1,43.8 158.7,44 99.3,45.75 114.1,48.7 125.3,49.5 158.7,50.5 114.2,51.4 109.4,54.1 112.2,54.4 114.2,54.5 116.9,54.5 119.6,54.5 124.9,54.5 128.8,54.5 132.9,54.5 139,54.5 144.2,54.5 149.8,54.5 154.8,54.5 158.9,54.5 135.2,54.7 111.2,55.8 114.2,56 135.3,58.2 158.9,58.3 114.2,59.1 135.3,61.6 135.2,65.8 59.75,71.1 89.05,71.8 33.15,71.95 94.65,73.4 57.2,75.2 114.2,76.2 135.3,78.8 79.946,79.246 83.5,79.5 0.9,81.9 114.3,81.9 135.3,82.4 114.3,84.1 114.5,87.3 83.5,87.9 0.9,88.3 153.1,90.4 127.9,90.5 130.8,90.5 135.3,90.5 140.9,90.5 158.8,90.5 19.2,93.95 60.55,95.25 19.25,95.5 0.9,107.2 75,110.25 79.95,110.25 38.9,112 28.6,112.1 68.6,112.1 12.7,112.2 20.5,112.2 48.9,112.2 59,112.2 75.8,112.2
  other v3: 158.85,13.55 114.158,41.114 145.1,41.1 147.2,81.1 114.197,90.405 146.55,90.5
  other v4: 126.207,17.088 124.707,23.688 125.207,23.688 126.207,23.688 126.75,66.35
  other v6: 37.9,48.9 39.1,48.9 40.3,48.9 37.9,50.1 39.1,50.1 37.9,51.3 39.1,51.3
  other v8: 103.175,12.7 101.75,45.675 60.75,59 84.475,61.975
  other v9: 82.4,65.55
  other v10: 102.5,50.4
GPS_ANT: U4.1 X6.1 | length 12.8
  Top Layer w0.15: U4.1@156.55,100.79 156.56,100.8 v2(157.95,100.8) ; v2@157.826,100.676 ccw(c157.528,100.378) 157.528,100.8 ccw(c157.528,101.222) v2@157.826,100.924
  Bottom Layer w0.15: v2@157.95,100.625 cw(c157.95,100.203) 158.249,100.501 cw(c158.547,100.8) v2@158.125,100.8 ; v2(157.95,100.8) 160.3,98.45 166.95,98.45 X6.1@167,98.5
INHIBIT: Q4.3 U16.3 U17.3 U34.3 | length 105.3
  Top Layer w0.2: v2@19.194,97.156 ccw(c18.858,97.492) U16.3@19.333,97.492 ; v2@19.333,97.083 U16.3@19.333,98.042 ; 19.333,97.332 ccw(c19.582,97.332) v2@19.406,97.156 ; v2@40.594,97.256 ccw(c40.355,97.495) U17.3@40.693,97.495 ; v2@40.693,97.157 U17.3@40.693,98.029 ; U17.3@40.693,97.529 ccw(c41.079,97.529) v2@40.806,97.256 ; v2@79.294,97.606 ccw(c78.958,97.942) U34.3@79.433,97.942 ; v2@79.433,97.533 U34.3@79.433,98.392 ; U34.3@79.433,97.782 ccw(c79.682,97.782) v2@79.506,97.606 ; v2@87.794,76.544 cw(c87.538,76.288) 87.9,76.288 cw(c88.262,76.288) v2@88.006,76.544 ; Q4.3@87.9,76.017 v2(87.9,76.65) v2@87.9,76.75
  Bottom Layer w0.2: v2(19.3,97.05) 20.1,97.85 39.95,97.85 40.65,97.15 57.8,97.15 58.55,97.9 62.025,97.9 62.775,97.15 77,97.15 77.9,98.05 78.85,98.05 v2(79.4,97.5) 75,93.1 75,79.05 77.4,76.65 87.8,76.65 v2@87.9,76.75 ; v2@19.3,97.2 ccw(c19.3,97.562) 19.556,97.306 ccw(c19.812,97.05) v2@19.45,97.05 ; 40.359,97.441 ccw(c40.7,97.783) v2@40.7,97.3 ; 40.479,97.321 cw(c40.309,97.15) v2@40.55,97.15 ; v2@40.806,97.044 cw(c41.062,96.788) 41.062,97.15 cw(c41.062,97.512) v2@40.806,97.256 ; 79.144,97.756 cw(c78.888,97.5) 79.25,97.5 cw(c78.888,97.5) 79.144,97.244 cw(c79.4,96.988) v2@79.4,97.35 ; 79.144,97.756 ccw(c79.4,98.012) v2@79.4,97.65 ; v2@87.794,76.544 ccw(c87.538,76.288) 87.538,76.65 ccw(c87.538,77.012) v2@87.794,76.756
  other v2: 40.7,97.15
INIT_B: Q2.1 R30.2 U8.T6 | length 22.1
  Top Layer w0.15: v1@70.45,51.325 cw(c70.45,50.782) U8.T6@70.834,51.166 ; v1(70.45,51.5) 70.5,51.5 U8.T6@71,51 ; v1@70.625,51.5 ccw(c70.927,51.5) 70.713,51.287 ; v2(74.65,65.25) 75.65,65.25 ; v2@74.774,65.126 cw(c75.072,64.828) 75.072,65.25 cw(c75.072,65.672) v2@74.774,65.374 ; Q2.1@75.6,64.55 75.65,64.6 75.65,65.25 ; R30.2@75.6,66.15 75.65,66.1 75.65,65.25
  MidLayer1 w0.15: v1(70.45,51.5) 71.95,53 72.6,53 72.675,53.075 72.925,53.324 72.925,53.675 73.125,53.875 73.5,53.875 74,54.375 74,55.8 74.65,56.45 v2(74.65,65.25) ; v1@70.45,51.675 ccw(c70.45,52.097) 70.749,51.799 ccw(c71.047,51.5) v1@70.625,51.5 ; v2@74.526,65.126 cw(c74.228,64.828) 74.65,64.828 cw(c75.072,64.828) v2@74.774,65.126
LED_DONE: LED1.1 Q1.3 | length 3.6
  Top Layer w0.15: Q1.3@167.5,12.3 167.55,12.25 LED1.1@167.55,8.77
LEDS1: LED1.2 U8.Y3 | length 134.8
  Top Layer w0.15: U8.Y3@74,55 v1(74.5,55.5) ; v1@74.325,55.5 cw(c73.903,55.5) 74.201,55.201 cw(c74.5,54.903) v1@74.5,55.325
  Mid-Layer 2 w0.15: v1@74.5,55.325 cw(c74.5,54.903) 74.799,55.201 cw(c75.097,55.5) v1@74.675,55.5 ; v1(74.5,55.5) 76.75,53.25 76.75,40.2 v2(84.35,32.6) ; v2@84.175,32.6 ccw(c83.753,32.6) 84.051,32.899 ccw(c84.35,33.197) v2@84.35,32.775
  Bottom Layer w0.15: v2@84.226,32.476 cw(c83.928,32.178) 84.35,32.178 cw(c84.772,32.178) v2@84.474,32.476 ; v2(84.35,32.6) 84.35,19.875 101.525,2.7 159.7,2.7 161.45,4.45 161.45,6.85 162,7.4 163.64,7.4 LED1.2@165.01,8.77
LEDS2: LED1.3 U8.W4 | length 131.3
  Top Layer w0.15: U8.W4@73,54 73.5,53.5 v1(73.5,53.45) ; U8.W4@73.166,53.834 cw(c72.782,53.45) v1@73.325,53.45 ; 73.287,53.713 ccw(c73.5,53.927) v1@73.5,53.625
  Mid-Layer 2 w0.15: v1@73.5,53.275 cw(c73.5,52.361) 74.146,53.007 ; v1@73.5,53.425 cw(c73.5,52.873) 73.89,53.263 ; v1(73.5,53.45) 73.704,53.45 76.1,51.054 76.1,39.15 v2(84.9,30.35) ; v2@84.725,30.35 ccw(c84.303,30.35) 84.601,30.649 ccw(c84.9,30.947) v2@84.9,30.525
  Bottom Layer w0.15: v2@84.776,30.226 cw(c84.659,30.109) 84.825,30.109 cw(c85.141,30.109) v2@84.918,30.332 ; 84.825,29.746 cw(c85.504,29.746) v2@85.024,30.226 ; v2(84.9,30.35) 84.825,30.275 84.825,19.895 101.67,3.05 159.65,3.05 161.1,4.5 161.1,7.4 LED1.3@162.47,8.77
LEDS3: LED2.1 U8.AB2 | length 149.1
  Top Layer w0.15: U8.AB2@75,57 75.45,57.45 75.5,57.45 v2(75.5,57.55) ; U8.AB2@75.166,57.166 ccw(c74.782,57.55) v2@75.325,57.55 ; 75.287,57.287 cw(c75.5,57.073) v2@75.5,57.375
  Mid-Layer 2 w0.15: v2@75.5,57.375 cw(c75.5,56.953) 75.799,57.251 cw(c76.097,57.55) v2@75.675,57.55 ; v2(75.5,57.55) 77.45,55.6 77.45,40.75 85.4,32.8 v2(85.4,32.3) ; v2@85.276,32.424 ccw(c84.978,32.722) 85.4,32.722 ccw(c85.822,32.722) v2@85.524,32.424
  Bottom Layer w0.15: v2@85.276,32.176 cw(c84.978,31.878) 85.4,31.878 cw(c85.822,31.878) v2@85.524,32.176 ; v2(85.4,32.3) 85.4,29.85 85.7,29.55 85.7,28.45 85.6,28.35 85.6,20.11 102.01,3.7 159.2,3.7 160.5,5 160.5,15.45 166.15,21.1 166.15,22.37 LED2.1@167.55,23.77
LEDS4: LED2.2 U8.Y4 | length 145.2
  Top Layer w0.15: U8.Y4@73,55 v1(73.5,54.5) ; v1@73.325,54.5 ccw(c72.903,54.5) 73.201,54.799 ccw(c73.5,55.097) v1@73.5,54.675
  Mid-Layer 2 w0.15: v1(73.5,54.5) 74.25,54.5 76.4,52.35 76.4,39.7 v2(85.95,30.15) ; v1@73.624,54.376 cw(c73.922,54.078) 73.922,54.5 cw(c73.922,54.922) v1@73.624,54.624 ; v2@85.775,30.15 ccw(c85.353,30.15) 85.651,30.449 ccw(c85.95,30.747) v2@85.95,30.325
  Bottom Layer w0.15: v2@85.826,30.026 cw(c85.528,29.728) 85.95,29.728 cw(c86.372,29.728) v2@86.074,30.026 ; v2(85.95,30.15) 85.95,28.35 85.95,20.255 102.155,4.05 159.055,4.05 160.15,5.145 160.15,15.7 163.75,19.3 163.75,22.51 LED2.2@165.01,23.77
LEDS5: LED2.3 U8.AA2 | length 144.5
  Top Layer w0.15: U8.AA2@75,56 75.4,56.4 75.4,56.45 75.45,56.5 v1(75.5,56.5) ; v1@75.325,56.5 cw(c74.903,56.5) 75.201,56.201 cw(c75.5,55.903) v1@75.5,56.325
  Mid-Layer 2 w0.15: v1@75.5,56.325 cw(c75.5,55.903) 75.799,56.201 cw(c76.097,56.5) v1@75.675,56.5 ; v1(75.5,56.5) 77.15,54.85 77.15,40.5 84.95,32.7 84.95,31.9 86.4,30.45 v2(86.4,29.55) ; v2@86.276,29.674 ccw(c85.978,29.972) 86.4,29.972 ccw(c86.822,29.972) v2@86.524,29.674
  Bottom Layer w0.15: 86.3,28.886 cw(c87.064,28.886) v2@86.524,29.426 ; 86.3,29.248 cw(c86.702,29.248) v2@86.418,29.532 ; v2(86.4,29.55) 86.3,29.45 86.3,20.4 102.35,4.35 158.931,4.35 159.85,5.269 159.85,21.15 LED2.3@162.47,23.77
LMS1_NRST: R95-1.1 U8.L3 U12-1.75 | length 72.3
  Top Layer w0.15: U8.L3@74,46 74.5,46.5 94.3,46.5 v1(94.9,45.9) ; v1@94.75,45.9 ccw(c94.388,45.9) 94.644,46.156 ccw(c94.9,46.412) v1@94.9,46.05
  Top Layer w0.2: U12-1.75@128.282,20.888 v1(129.107,20.888) ; v1@129.019,20.8 ccw(c128.805,20.586) 128.805,20.888 ccw(c128.805,21.19) v1@129.019,20.976
  MidLayer1 w0.15: v1(94.9,45.9) 98.3,45.9 114.8,29.4 121.1,29.4 126.832,23.668 126.832,22.033 127.102,21.763 127.201,21.763 128.076,20.888 v1(129.107,20.888) ; v1@95.006,45.794 cw(c95.262,45.538) 95.262,45.9 cw(c95.262,46.262) v1@95.006,46.006 ; v1@129.001,20.782 ccw(c128.745,20.526) 128.745,20.888 ccw(c128.745,21.25) v1@129.001,20.994
  Bottom Layer w0.2: v1(129.107,20.888) 129.107,21.053 129.336,21.282 ; v1@129.229,20.915 cw(c129.617,21.001) 129.336,21.282 ; R95-1.1@130.407,22.088 130.177,21.858 129.711,21.858 129.336,21.483 129.336,21.282
LMS2_NRST: R95-2.1 U8.Y1 U12-2.75 | length 69.3
  Top Layer w0.15: U8.Y1@76,55 80.5,55 v1(80.525,54.975) ; 80.103,55 cw(c80.103,54.553) v1@80.419,54.869 ; 80.223,55 ccw(c80.223,55.277) v1@80.419,55.081
  Top Layer w0.2: U12-2.75@128.321,70.18 v1(129.146,70.18) ; v1@129.058,70.091 ccw(c128.844,69.878) 128.844,70.18 ccw(c128.844,70.482) v1@129.058,70.268
  MidLayer1 w0.15: v1(80.525,54.975) 81.45,55.9 81.45,57.35 97.742,73.642 117.143,73.642 117.376,73.875 122.539,73.875 123.827,72.587 126.443,72.587 126.871,72.159 126.871,71.325 127.141,71.055 127.24,71.055 128.115,70.18 v1(129.146,70.18) ; v1@80.525,55.125 ccw(c80.525,55.487) 80.781,55.231 ccw(c81.037,54.975) v1@80.675,54.975 ; v1@129.04,70.074 ccw(c128.784,69.818) 128.784,70.18 ccw(c128.784,70.542) v1@129.04,70.286
  Bottom Layer w0.2: v1(129.146,70.18) 129.146,70.345 129.375,70.574 ; v1@129.268,70.207 cw(c129.656,70.293) 129.375,70.574 ; R95-2.1@130.446,71.38 130.216,71.15 129.75,71.15 129.375,70.775 129.375,70.574
M0: R31.1 U8.AA22 | length 2.8
  Top Layer w0.15: v2(54.4,56) U8.AA22@55,56 ; v2@54.524,55.876 cw(c54.822,55.578) 54.822,56 cw(c54.822,56.422) v2@54.524,56.124
  Bottom Layer w0.15: R31.1@53.5,56.05 53.55,56 v2(54.4,56) ; v2@54.276,55.876 ccw(c53.978,55.578) 53.978,56 ccw(c53.978,56.422) v2@54.276,56.124
M1: R32.1 U8.U15 | length 2.4
  Top Layer w0.2: U8.U15@62,52 62.05,52 v1(62.55,52.5) ; v1@62.425,52.5 cw(c62.123,52.5) 62.337,52.287 cw(c62.55,52.073) v1@62.55,52.375
  Bottom Layer w0.2: v1@62.462,52.588 ccw(c62.128,52.922) R32.1@62.6,52.922 ; v1(62.55,52.5) 62.6,52.5 62.6,53.15 R32.1@62.65,53.2
MDC: U8.F22 U9.55 | length 17.5
  Top Layer w0.15: U9.55@39.3,44.625 39.3,44.1 39.5,43.9 39.65,43.9 42.55,41 U8.F22@55,41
